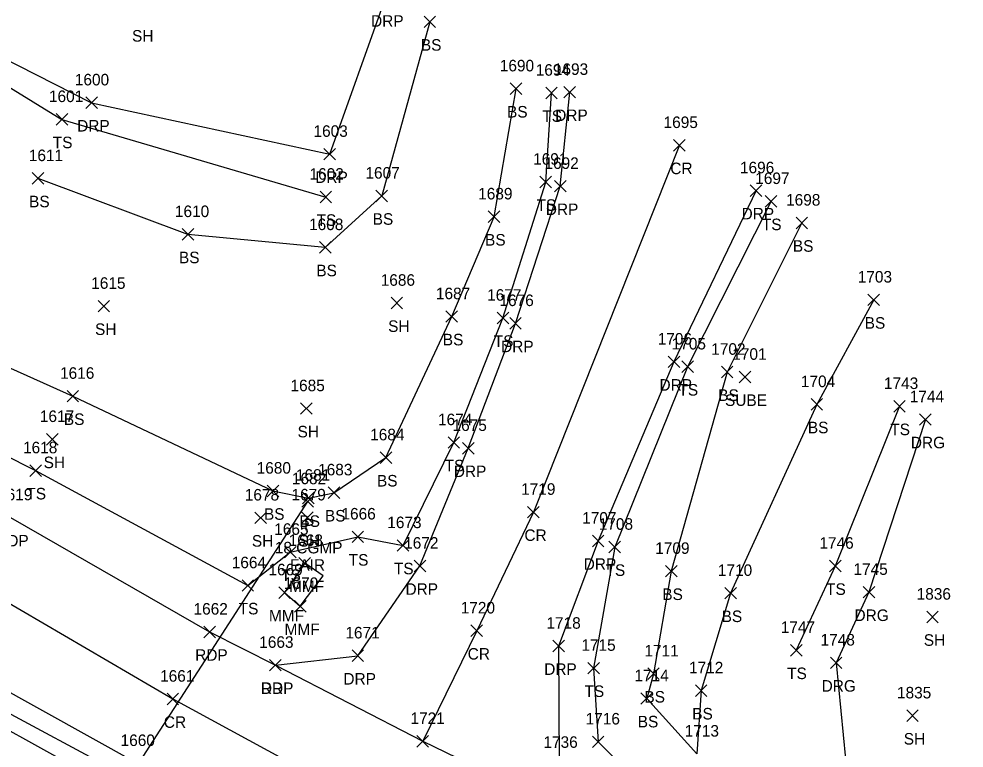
# Model space of a CAD drawing. Extents: x 1586965 to 1590952, y 716317 to 720029.
# Drawn here: x 1587975.1 to 1588139.1, y 719743.2 to 719869.6 of the extents above; entities that cross this region are included whole.
import ezdxf

# ---------------------------------------------------------------- set-up
doc = ezdxf.new("R2010")
doc.units = 0
for name, color, linetype in [('D_A', 7, 'Continuous'), ('D_C', 7, 'Continuous'), ('D_I', 7, 'Continuous'), ('D_TIC', 7, 'Continuous'), ('DCP', 7, 'Continuous'), ('L_A', 7, 'Continuous'), ('L_I', 7, 'Continuous'), ('L_TIC', 7, 'Continuous'), ('LDEFAULT', 7, 'Continuous'), ('LELB', 7, 'Continuous'), ('P_A', 7, 'Continuous'), ('P_I', 7, 'Continuous'), ('P_TIC', 7, 'Continuous'), ('PET', 7, 'Continuous'), ('PRC', 7, 'Continuous'), ('R_A', 7, 'Continuous'), ('R_I', 7, 'Continuous'), ('R_TIC', 7, 'Continuous'), ('RDG', 7, 'Continuous'), ('RDP', 7, 'Continuous'), ('U_A', 7, 'Continuous'), ('U_I', 7, 'Continuous'), ('U_TIC', 7, 'Continuous')]:
    doc.layers.add(name, color=color, linetype=linetype)

msp = doc.modelspace()

# ---------------------------------------------------------------- linework, layer by layer
at = {"layer": 'D_TIC'}
for points in [[(1588024.22, 719784.95), (1588026.22, 719786.95)], [(1588026.22, 719784.95), (1588024.22, 719786.95)]]:
    msp.add_lwpolyline(points, dxfattribs=at)
at = {"layer": 'DCP'}
msp.add_lwpolyline([(1587993.11, 719736.22), (1588025.22, 719785.95)], dxfattribs=at)
at = {"layer": 'L_TIC'}
for points in [[(1588045.42, 719868.11), (1588047.42, 719870.11)], [(1588047.42, 719868.11), (1588045.42, 719870.11)], [(1588060.37, 719856.52), (1588062.37, 719858.52)], [(1588062.37, 719856.52), (1588060.37, 719858.52)], [(1588066.52, 719855.77), (1588068.52, 719857.77)], [(1588068.52, 719855.77), (1588066.52, 719857.77)], [(1587981.59, 719851.2), (1587983.59, 719853.2)], [(1587983.59, 719851.2), (1587981.59, 719853.2)], [(1587977.45, 719840.96), (1587979.45, 719842.96)], [(1587979.45, 719840.96), (1587977.45, 719842.96)], [(1588065.51, 719840.34), (1588067.51, 719842.34)], [(1588067.51, 719840.34), (1588065.51, 719842.34)], [(1588027.36, 719837.74), (1588029.36, 719839.74)], [(1588029.36, 719837.74), (1588027.36, 719839.74)], [(1588037.06, 719837.93), (1588039.06, 719839.93)], [(1588039.06, 719837.93), (1588037.06, 719839.93)], [(1588104.6, 719836.99), (1588106.6, 719838.99)], [(1588106.6, 719836.99), (1588104.6, 719838.99)], [(1588056.55, 719834.32), (1588058.55, 719836.32)], [(1588058.55, 719834.32), (1588056.55, 719836.32)], [(1588109.95, 719833.25), (1588111.95, 719835.25)], [(1588111.95, 719833.25), (1588109.95, 719835.25)], [(1588003.45, 719831.26), (1588005.45, 719833.26)], [(1588005.45, 719831.26), (1588003.45, 719833.26)], [(1588027.28, 719829), (1588029.28, 719831)], [(1588029.28, 719829), (1588027.28, 719831)], [(1587988.85, 719818.82), (1587990.85, 719820.82)], [(1587990.85, 719818.82), (1587988.85, 719820.82)], [(1588039.69, 719819.35), (1588041.69, 719821.35)], [(1588041.69, 719819.35), (1588039.69, 719821.35)], [(1588122.41, 719819.91), (1588124.41, 719821.91)], [(1588124.41, 719819.91), (1588122.41, 719821.91)], [(1588049.21, 719817.02), (1588051.21, 719819.02)], [(1588051.21, 719817.02), (1588049.21, 719819.02)], [(1588058.09, 719816.76), (1588060.09, 719818.76)], [(1588060.09, 719816.76), (1588058.09, 719818.76)], [(1588090.13, 719808.31), (1588092.13, 719810.31)], [(1588092.13, 719808.31), (1588090.13, 719810.31)], [(1588097, 719807.39), (1588099, 719809.39)], [(1588099, 719807.39), (1588097, 719809.39)], [(1587983.49, 719803.22), (1587985.49, 719805.22)], [(1587985.49, 719803.22), (1587983.49, 719805.22)], [(1588023.98, 719801.07), (1588025.98, 719803.07)], [(1588025.98, 719801.07), (1588023.98, 719803.07)], [(1588112.55, 719801.78), (1588114.55, 719803.78)], [(1588114.55, 719801.78), (1588112.55, 719803.78)], [(1588126.88, 719801.45), (1588128.88, 719803.45)], [(1588128.88, 719801.45), (1588126.88, 719803.45)], [(1587979.94, 719795.73), (1587981.94, 719797.73)], [(1587981.94, 719795.73), (1587979.94, 719797.73)], [(1588049.57, 719795.18), (1588051.57, 719797.18)], [(1588051.57, 719795.18), (1588049.57, 719797.18)], [(1588037.8, 719792.55), (1588039.8, 719794.55)], [(1588039.8, 719792.55), (1588037.8, 719794.55)], [(1587977.02, 719790.31), (1587979.02, 719792.31)], [(1587979.02, 719790.31), (1587977.02, 719792.31)], [(1588018.19, 719786.78), (1588020.19, 719788.78)], [(1588020.19, 719786.78), (1588018.19, 719788.78)], [(1588028.77, 719786.48), (1588030.77, 719788.48)], [(1588030.77, 719786.48), (1588028.77, 719788.48)], [(1588024.35, 719785.55), (1588026.35, 719787.55)], [(1588026.35, 719785.55), (1588024.35, 719787.55)], [(1588016.05, 719782.12), (1588018.05, 719784.12)], [(1588018.05, 719782.12), (1588016.05, 719784.12)], [(1588024.17, 719782.14), (1588026.17, 719784.14)], [(1588026.17, 719782.14), (1588024.17, 719784.14)], [(1588032.93, 719778.83), (1588034.93, 719780.83)], [(1588034.93, 719778.83), (1588032.93, 719780.83)], [(1588021.21, 719776.17), (1588023.21, 719778.17)], [(1588023.21, 719776.17), (1588021.21, 719778.17)], [(1588040.77, 719777.33), (1588042.77, 719779.33)], [(1588042.77, 719777.33), (1588040.77, 719779.33)], [(1588077.49, 719777.05), (1588079.49, 719779.05)], [(1588079.49, 719777.05), (1588077.49, 719779.05)], [(1588023.71, 719774.24), (1588025.71, 719776.24)], [(1588025.71, 719774.24), (1588023.71, 719776.24)], [(1588087.3, 719772.87), (1588089.3, 719774.87)], [(1588089.3, 719772.87), (1588087.3, 719774.87)], [(1588115.74, 719773.76), (1588117.74, 719775.76)], [(1588117.74, 719773.76), (1588115.74, 719775.76)], [(1588013.84, 719770.38), (1588015.84, 719772.38)], [(1588015.84, 719770.38), (1588013.84, 719772.38)], [(1588020.21, 719769.15), (1588022.21, 719771.15)], [(1588022.21, 719769.15), (1588020.21, 719771.15)], [(1588097.59, 719769.05), (1588099.59, 719771.05)], [(1588099.59, 719769.05), (1588097.59, 719771.05)], [(1588022.93, 719766.79), (1588024.93, 719768.79)], [(1588024.93, 719766.79), (1588022.93, 719768.79)], [(1588132.61, 719764.93), (1588134.61, 719766.93)], [(1588134.61, 719764.93), (1588132.61, 719766.93)], [(1588108.98, 719759.16), (1588110.98, 719761.16)], [(1588110.98, 719759.16), (1588108.98, 719761.16)], [(1588073.83, 719756.06), (1588075.83, 719758.06)], [(1588075.83, 719756.06), (1588073.83, 719758.06)], [(1588084.2, 719755.09), (1588086.2, 719757.09)], [(1588086.2, 719755.09), (1588084.2, 719757.09)], [(1588092.49, 719752.16), (1588094.49, 719754.16)], [(1588094.49, 719752.16), (1588092.49, 719754.16)], [(1588083.04, 719750.79), (1588085.04, 719752.79)], [(1588085.04, 719750.79), (1588083.04, 719752.79)], [(1588083.04, 719750.79), (1588085.04, 719752.79)], [(1588085.04, 719750.79), (1588083.04, 719752.79)], [(1588129.14, 719747.81), (1588131.14, 719749.81)], [(1588131.14, 719747.81), (1588129.14, 719749.81)], [(1588074.62, 719743.29), (1588076.62, 719745.29)], [(1588076.62, 719743.29), (1588074.62, 719745.29)]]:
    msp.add_lwpolyline(points, dxfattribs=at)
at = {"layer": 'LDEFAULT'}
for points in [[(1588027.89, 719773.06), (1588024.71, 719775.24), (1588021.21, 719770.15), (1588023.93, 719767.79)], [(1588023.93, 719767.79), (1588027.89, 719773.06)]]:
    msp.add_lwpolyline(points, dxfattribs=at)
at = {"layer": 'LELB'}
for points in [[(1587811.93, 719949.52), (1587792.29, 719924.28), (1587790.61, 719906.24), (1587796.42, 719891.05), (1587800.94, 719879.86), (1587824.09, 719870.75), (1587863.89, 719860.75), (1587885.59, 719851.77), (1587915.12, 719838.63), (1587948, 719820.59), (1587984.49, 719804.22), (1588019.19, 719787.78), (1588025.35, 719786.55), (1588029.77, 719787.48), (1588038.8, 719793.55), (1588050.21, 719818.02), (1588057.55, 719835.32), (1588061.37, 719857.52)], [(1587811.93, 719949.52), (1587792.29, 719924.28), (1587790.61, 719906.24), (1587796.42, 719891.05), (1587800.94, 719879.86), (1587824.09, 719870.75), (1587863.89, 719860.75), (1587885.59, 719851.77), (1587915.12, 719838.63), (1587948, 719820.59), (1587984.49, 719804.22), (1588019.19, 719787.78), (1588025.35, 719786.55), (1588029.77, 719787.48), (1588038.8, 719793.55), (1588050.21, 719818.02), (1588057.55, 719835.32), (1588061.37, 719857.52)], [(1587980.38, 719907.57), (1587967.76, 719883.76), (1587958.41, 719867.03), (1587982.59, 719852.2), (1588028.36, 719838.74)], [(1587980.38, 719907.57), (1587967.76, 719883.76), (1587958.41, 719867.03), (1587982.59, 719852.2), (1588028.36, 719838.74)], [(1587785.92, 719905.04), (1587790.72, 719880.4), (1587795.97, 719870.23), (1587799.98, 719865.36), (1587821.67, 719859.64), (1587858.86, 719846.91), (1587879.62, 719839.86), (1587909.63, 719826.79), (1587942.7, 719809.1), (1587978.02, 719791.31), (1588014.84, 719771.38), (1588022.21, 719777.17), (1588033.93, 719779.83), (1588041.77, 719778.33), (1588050.57, 719796.18), (1588059.09, 719817.76), (1588066.51, 719841.34), (1588067.52, 719856.77)], [(1587785.92, 719905.04), (1587790.72, 719880.4), (1587795.97, 719870.23), (1587799.98, 719865.36), (1587821.67, 719859.64), (1587858.86, 719846.91), (1587879.62, 719839.86), (1587909.63, 719826.79), (1587942.7, 719809.1), (1587978.02, 719791.31), (1588014.84, 719771.38), (1588022.21, 719777.17), (1588033.93, 719779.83), (1588041.77, 719778.33), (1588050.57, 719796.18), (1588059.09, 719817.76), (1588066.51, 719841.34), (1588067.52, 719856.77)], [(1588046.42, 719869.11), (1588038.06, 719838.93), (1588028.28, 719830), (1588004.45, 719832.26), (1587978.45, 719841.96)], [(1588046.42, 719869.11), (1588038.06, 719838.93), (1588028.28, 719830), (1588004.45, 719832.26), (1587978.45, 719841.96)], [(1588105.6, 719837.99), (1588091.13, 719809.31), (1588078.49, 719778.05), (1588074.83, 719757.06), (1588075.62, 719744.29), (1588082.54, 719737.39), (1588094.48, 719728.45), (1588105.69, 719715.8), (1588135.44, 719702.09)], [(1588105.6, 719837.99), (1588091.13, 719809.31), (1588078.49, 719778.05), (1588074.83, 719757.06), (1588075.62, 719744.29), (1588082.54, 719737.39), (1588094.48, 719728.45), (1588105.69, 719715.8), (1588135.44, 719702.09)], [(1588110.95, 719834.25), (1588098, 719808.39), (1588088.3, 719773.87), (1588085.2, 719756.09), (1588084.04, 719751.79)], [(1588110.95, 719834.25), (1588098, 719808.39), (1588088.3, 719773.87), (1588085.2, 719756.09), (1588084.04, 719751.79)], [(1587769.54, 719828.25), (1587817.81, 719818.92), (1587845.39, 719810.87), (1587866.59, 719802.16), (1587894.5, 719791.41), (1587924.64, 719774.45), (1587960.66, 719756.07), (1587994.24, 719738.05), (1588029.81, 719715.93), (1588049.13, 719705.79), (1588061.35, 719699.86), (1588090.7, 719682.25), (1588125.12, 719667.08), (1588163.84, 719653.66), (1588168.64, 719652.01), (1588170.5, 719647.84), (1588169.34, 719638.56), (1588158.94, 719617.68), (1588144.69, 719590.38)], [(1587769.54, 719828.25), (1587817.81, 719818.92), (1587845.39, 719810.87), (1587866.59, 719802.16), (1587894.5, 719791.41), (1587924.64, 719774.45), (1587960.66, 719756.07), (1587994.24, 719738.05), (1588029.81, 719715.93), (1588049.13, 719705.79), (1588061.35, 719699.86), (1588090.7, 719682.25), (1588125.12, 719667.08), (1588163.84, 719653.66), (1588168.64, 719652.01), (1588170.5, 719647.84), (1588169.34, 719638.56), (1588158.94, 719617.68), (1588144.69, 719590.38)], [(1588123.41, 719820.91), (1588113.55, 719802.78), (1588098.59, 719770.05), (1588093.49, 719753.16), (1588092.75, 719742.19), (1588084.04, 719751.79)], [(1588123.41, 719820.91), (1588113.55, 719802.78), (1588098.59, 719770.05), (1588093.49, 719753.16), (1588092.75, 719742.19), (1588084.04, 719751.79)], [(1588127.88, 719802.45), (1588116.74, 719774.76), (1588109.98, 719760.16)], [(1588127.88, 719802.45), (1588116.74, 719774.76), (1588109.98, 719760.16)], [(1587893.61, 719788.22), (1587923.32, 719772.46), (1587959.45, 719753.99), (1587990.31, 719736.86), (1587992.49, 719736.59), (1587993.47, 719735.49), (1587996.7, 719733.15), (1588001.37, 719729.89), (1588028.07, 719713.52), (1588047.21, 719701.72), (1588059.27, 719695.66), (1588101.54, 719672.79), (1588123.97, 719663.55), (1588153.31, 719655.21), (1588167.62, 719650.14)], [(1587893.61, 719788.22), (1587923.32, 719772.46), (1587959.45, 719753.99), (1587990.31, 719736.86), (1587992.49, 719736.59), (1587993.47, 719735.49), (1587996.7, 719733.15), (1588001.37, 719729.89), (1588028.07, 719713.52), (1588047.21, 719701.72), (1588059.27, 719695.66), (1588101.54, 719672.79), (1588123.97, 719663.55), (1588153.31, 719655.21), (1588167.62, 719650.14)]]:
    msp.add_lwpolyline(points, dxfattribs=at)
at = {"layer": 'P_TIC'}
for points in [[(1588088.7, 719846.7), (1588090.7, 719848.7)], [(1588090.7, 719846.7), (1588088.7, 719848.7)], [(1588063.38, 719783.11), (1588065.38, 719785.11)], [(1588065.38, 719783.11), (1588063.38, 719785.11)], [(1588007.21, 719762.34), (1588009.21, 719764.34)], [(1588009.21, 719762.34), (1588007.21, 719764.34)], [(1588053.55, 719762.54), (1588055.55, 719764.54)], [(1588055.55, 719762.54), (1588053.55, 719764.54)], [(1588018.61, 719756.58), (1588020.61, 719758.58)], [(1588020.61, 719756.58), (1588018.61, 719758.58)], [(1588000.84, 719750.71), (1588002.84, 719752.71)], [(1588002.84, 719750.71), (1588000.84, 719752.71)], [(1588044.18, 719743.38), (1588046.18, 719745.38)], [(1588046.18, 719743.38), (1588044.18, 719745.38)], [(1588044.18, 719743.38), (1588046.18, 719745.38)], [(1588046.18, 719743.38), (1588044.18, 719745.38)]]:
    msp.add_lwpolyline(points, dxfattribs=at)
at = {"layer": 'PET'}
for points in [[(1587795.98, 719858.74), (1587820.3, 719853.13), (1587857.37, 719841.42), (1587877.69, 719833.83), (1587907.04, 719819.84), (1587939.32, 719802.03), (1587973.69, 719783.16), (1588008.21, 719763.34), (1588019.61, 719757.58), (1588045.18, 719744.38), (1588072.84, 719731.02), (1588081.8, 719723.85), (1588104.43, 719712.22), (1588133.68, 719697.26), (1588170.87, 719681.39), (1588198.42, 719670.99), (1588228.28, 719659.25)], [(1587769.59, 719834.05), (1587819.16, 719826.14), (1587848.36, 719816.77), (1587868.73, 719807.9), (1587895.82, 719795.75), (1587926.99, 719779.02), (1587962.24, 719759.15), (1587995.65, 719740.56), (1588031.83, 719719.54), (1588060.89, 719703.68), (1588093.53, 719688.06), (1588127.35, 719672.7), (1588165.1, 719657.02), (1588195.68, 719645.12), (1588212.38, 719637.86), (1588219.86, 719635.29)]]:
    msp.add_lwpolyline(points, dxfattribs=at)
at = {"layer": 'PRC'}
for points in [[(1588089.7, 719847.7), (1588064.38, 719784.11), (1588054.55, 719763.54), (1588045.18, 719744.38)], [(1588089.7, 719847.7), (1588064.38, 719784.11), (1588054.55, 719763.54), (1588045.18, 719744.38)], [(1587770.57, 719846.88), (1587822.37, 719838.71), (1587852.49, 719828.95), (1587873.58, 719820.04), (1587901.35, 719807.55), (1587933.49, 719790.19), (1587967.95, 719771.53), (1588001.84, 719751.71), (1588038.72, 719731.7), (1588068.79, 719715.56), (1588099.02, 719700.65), (1588127.2, 719686.75), (1588167.73, 719669.46), (1588194.58, 719658.84), (1588224.51, 719647.27)], [(1587770.57, 719846.88), (1587822.37, 719838.71), (1587852.49, 719828.95), (1587873.58, 719820.04), (1587901.35, 719807.55), (1587933.49, 719790.19), (1587967.95, 719771.53), (1588001.84, 719751.71), (1588038.72, 719731.7), (1588068.79, 719715.56), (1588099.02, 719700.65), (1588127.2, 719686.75), (1588167.73, 719669.46), (1588194.58, 719658.84), (1588224.51, 719647.27)]]:
    msp.add_lwpolyline(points, dxfattribs=at)
at = {"layer": 'R_TIC'}
for points in [[(1588069.67, 719855.91), (1588071.67, 719857.91)], [(1588071.67, 719855.91), (1588069.67, 719857.91)], [(1587986.74, 719854.09), (1587988.74, 719856.09)], [(1587988.74, 719854.09), (1587986.74, 719856.09)], [(1588028.05, 719845.17), (1588030.05, 719847.17)], [(1588030.05, 719845.17), (1588028.05, 719847.17)], [(1588068.04, 719839.61), (1588070.04, 719841.61)], [(1588070.04, 719839.61), (1588068.04, 719841.61)], [(1588102, 719838.85), (1588104, 719840.85)], [(1588104, 719838.85), (1588102, 719840.85)], [(1588060.28, 719815.83), (1588062.28, 719817.83)], [(1588062.28, 719815.83), (1588060.28, 719817.83)], [(1588087.76, 719809.16), (1588089.76, 719811.16)], [(1588089.76, 719809.16), (1588087.76, 719811.16)], [(1588131.37, 719799.17), (1588133.37, 719801.17)], [(1588133.37, 719799.17), (1588131.37, 719801.17)], [(1588052.09, 719794.18), (1588054.09, 719796.18)], [(1588054.09, 719794.18), (1588052.09, 719796.18)], [(1588074.61, 719778.11), (1588076.61, 719780.11)], [(1588076.61, 719778.11), (1588074.61, 719780.11)], [(1588043.7, 719773.77), (1588045.7, 719775.77)], [(1588045.7, 719773.77), (1588043.7, 719775.77)], [(1588121.59, 719769.23), (1588123.59, 719771.23)], [(1588123.59, 719769.23), (1588121.59, 719771.23)], [(1588067.76, 719759.89), (1588069.76, 719761.89)], [(1588069.76, 719759.89), (1588067.76, 719761.89)], [(1588032.93, 719758.21), (1588034.93, 719760.21)], [(1588034.93, 719758.21), (1588032.93, 719760.21)], [(1588018.61, 719756.58), (1588020.61, 719758.58)], [(1588020.61, 719756.58), (1588018.61, 719758.58)], [(1588115.89, 719756.98), (1588117.89, 719758.98)], [(1588117.89, 719756.98), (1588115.89, 719758.98)]]:
    msp.add_lwpolyline(points, dxfattribs=at)
at = {"layer": 'RDG'}
msp.add_lwpolyline([(1588132.37, 719800.17), (1588122.59, 719770.23), (1588116.89, 719757.98), (1588119.75, 719728.86)], dxfattribs=at)
at = {"layer": 'RDP'}
for points in [[(1587981.59, 719906.83), (1587969.62, 719882.82), (1587961.99, 719868.1), (1587987.74, 719855.09), (1588029.05, 719846.17), (1588038.73, 719873.26)], [(1588019.61, 719757.58), (1588033.93, 719759.21), (1588044.7, 719774.77), (1588053.09, 719795.18), (1588061.28, 719816.83), (1588069.04, 719840.61), (1588070.67, 719856.91)], [(1588103, 719839.85), (1588088.76, 719810.16), (1588075.61, 719779.11), (1588068.76, 719760.89), (1588068.87, 719740.24), (1588072.84, 719731.02)]]:
    msp.add_lwpolyline(points, dxfattribs=at)
at = {"layer": 'U_TIC'}
for points in [[(1588100.09, 719806.52), (1588102.09, 719808.52)], [(1588102.09, 719806.52), (1588100.09, 719808.52)]]:
    msp.add_lwpolyline(points, dxfattribs=at)

# ---------------------------------------------------------------- texts
at = {"layer": 'D_A'}
msp.add_text('P', height=2, dxfattribs=at).set_placement((1588024.6, 719780.95))
at = {"layer": 'D_C'}
for s, p in [('18 CGMP', (1588019.52, 719776.95)), (' FAIR', (1588021.4, 719773.95))]:
    msp.add_text(s, height=2, dxfattribs=at).set_placement(p)
at = {"layer": 'D_I'}
msp.add_text('1682', height=2, dxfattribs=at).set_placement((1588022.48, 719788.95))
at = {"layer": 'L_A'}
for s, p in [('SH', (1587994.75, 719865.68)), ('BS', (1588044.86, 719864.11)), ('BS', (1588059.81, 719852.52)), ('TS', (1588065.93, 719851.77)), ('TS', (1587981, 719847.2)), ('BS', (1587976.89, 719836.96)), ('TS', (1588064.92, 719836.34)), ('TS', (1588026.77, 719833.74)), ('BS', (1588036.5, 719833.93)), ('TS', (1588104.01, 719832.99)), ('BS', (1588055.99, 719830.32)), ('BS', (1588109.39, 719829.25)), ('BS', (1588002.89, 719827.26)), ('BS', (1588026.72, 719825)), ('BS', (1588121.85, 719815.91)), ('SH', (1587988.33, 719814.82)), ('SH', (1588039.18, 719815.35)), ('BS', (1588048.66, 719813.02)), ('TS', (1588057.5, 719812.76)), ('TS', (1588089.54, 719804.31)), ('BS', (1588096.44, 719803.39)), ('BS', (1587982.93, 719799.22)), ('BS', (1588111.99, 719797.78)), ('TS', (1588126.29, 719797.45)), ('SH', (1588023.47, 719797.07)), ('SH', (1587979.42, 719791.73)), ('TS', (1588048.98, 719791.18)), ('BS', (1588037.24, 719788.55)), ('TS', (1587976.42, 719786.31)), ('BS', (1588017.64, 719782.78)), ('BS', (1588023.79, 719781.55)), ('BS', (1588028.21, 719782.48)), ('SH', (1588015.54, 719778.12)), ('SH', (1588023.66, 719778.14)), ('TS', (1588032.34, 719774.83)), ('TS', (1588040.18, 719773.33)), ('TS', (1588076.89, 719773.05)), ('TS', (1588020.62, 719772.17)), ('MMF', (1588021.99, 719770.24)), ('TS', (1588115.15, 719769.76)), ('BS', (1588086.74, 719768.87)), ('TS', (1588013.25, 719766.38)), ('MMF', (1588018.5, 719765.15)), ('BS', (1588097.03, 719765.05)), ('MMF', (1588021.21, 719762.79)), ('SH', (1588132.1, 719760.93)), ('TS', (1588108.39, 719755.16)), ('TS', (1588073.24, 719752.06)), ('BS', (1588083.64, 719751.09)), ('BS', (1588082.48, 719746.79)), ('BS', (1588082.48, 719746.79)), ('BS', (1588091.93, 719748.16)), ('SH', (1588128.63, 719743.81))]:
    msp.add_text(s, height=2, dxfattribs=at).set_placement(p)
at = {"layer": 'L_I'}
for s, p in [('1690', (1588058.55, 719860.52)), ('1694', (1588064.78, 719859.77)), ('1601', (1587980.34, 719855.2)), ('1611', (1587976.85, 719844.96)), ('1691', (1588064.33, 719844.34)), ('1602', (1588025.54, 719841.74)), ('1607', (1588035.24, 719841.93)), ('1697', (1588102.86, 719840.99)), ('1689', (1588054.8, 719838.32)), ('1698', (1588108.21, 719837.25)), ('1610', (1588002.19, 719835.26)), ('1608', (1588025.46, 719833)), ('1703', (1588120.64, 719823.91)), ('1615', (1587987.67, 719822.82)), ('1686', (1588037.89, 719823.35)), ('1687', (1588047.47, 719821.02)), ('1677', (1588056.35, 719820.76)), ('1705', (1588088.36, 719812.31)), ('1702', (1588095.23, 719811.39)), ('1616', (1587982.26, 719807.22)), ('1704', (1588110.78, 719805.78)), ('1685', (1588022.24, 719805.07)), ('1743', (1588125.19, 719805.45)), ('1617', (1587978.76, 719799.73)), ('1674', (1588047.83, 719799.18)), ('1684', (1588036.06, 719796.55)), ('1618', (1587975.84, 719794.31)), ('1680', (1588016.37, 719790.78)), ('1681', (1588023.18, 719789.55)), ('1683', (1588027.03, 719790.48)), ('1678', (1588014.31, 719786.12)), ('1679', (1588022.42, 719786.14)), ('1666', (1588031.08, 719782.83)), ('1673', (1588039.03, 719781.33)), ('1708', (1588075.71, 719781.05)), ('1665', (1588019.42, 719780.17)), ('1668', (1588021.92, 719778.24)), ('1746', (1588113.99, 719777.76)), ('1709', (1588085.52, 719776.87)), ('1664', (1588012.05, 719774.38)), ('1669', (1588018.42, 719773.15)), ('1710', (1588096.38, 719773.05)), ('1670', (1588021.1, 719770.79)), ('1836', (1588130.86, 719768.93)), ('1747', (1588107.29, 719763.16)), ('1715', (1588072.7, 719760.06)), ('1711', (1588083.64, 719759.09)), ('1714', (1588081.91, 719754.79)), ('1714', (1588081.91, 719754.79)), ('1712', (1588091.37, 719756.16)), ('1835', (1588127.45, 719751.81)), ('1716', (1588073.44, 719747.29)), ('1713', (1588090.62, 719745.19))]:
    msp.add_text(s, height=2, dxfattribs=at).set_placement(p)
at = {"layer": 'P_A'}
for s, p in [('CR', (1588088.13, 719842.7)), ('RDP', (1587971.18, 719778.16)), ('CR', (1588062.82, 719779.11)), ('RDP', (1588005.7, 719758.34)), ('CR', (1588052.98, 719758.54)), ('RDP', (1588017.1, 719752.58)), ('CR', (1588000.27, 719746.71))]:
    msp.add_text(s, height=2, dxfattribs=at).set_placement(p)
at = {"layer": 'P_I'}
for s, p in [('1695', (1588086.96, 719850.7)), ('1619', (1587971.51, 719786.16)), ('1719', (1588062.25, 719787.11)), ('1662', (1588005.42, 719766.34)), ('1720', (1588051.77, 719766.54)), ('1663', (1588016.82, 719760.58)), ('1661', (1587999.62, 719754.71)), ('1721', (1588043.06, 719747.38)), ('1721', (1588043.06, 719747.38)), ('1660', (1587992.77, 719743.56))]:
    msp.add_text(s, height=2, dxfattribs=at).set_placement(p)
at = {"layer": 'R_A'}
for s, p in [('DRP', (1588036.22, 719868.26)), ('DRP', (1588068.16, 719851.91)), ('DRP', (1587985.23, 719850.09)), ('DRP', (1588026.54, 719841.17)), ('DRP', (1588066.53, 719835.61)), ('DRP', (1588100.49, 719834.85)), ('DRP', (1588058.77, 719811.83)), ('DRP', (1588086.25, 719805.16)), ('DRG', (1588129.85, 719795.17)), ('DRP', (1588050.57, 719790.18)), ('DRP', (1588073.1, 719774.11)), ('DRP', (1588042.19, 719769.77)), ('DRG', (1588120.08, 719765.23)), ('DRP', (1588066.25, 719755.89)), ('DRP', (1588031.42, 719754.21)), ('DRP', (1588017.1, 719752.58)), ('DRG', (1588114.38, 719752.98))]:
    msp.add_text(s, height=2, dxfattribs=at).set_placement(p)
at = {"layer": 'R_I'}
for s, p in [('1693', (1588067.93, 719859.91)), ('1600', (1587984.83, 719858.09)), ('1603', (1588026.23, 719849.17)), ('1692', (1588066.3, 719843.61)), ('1696', (1588100.21, 719842.85)), ('1676', (1588058.49, 719819.83)), ('1706', (1588085.94, 719813.16)), ('1744', (1588129.67, 719803.17)), ('1675', (1588050.35, 719798.18)), ('1707', (1588072.84, 719782.11)), ('1672', (1588041.96, 719777.77)), ('1745', (1588119.9, 719773.23)), ('1718', (1588066.64, 719763.89)), ('1671', (1588031.76, 719762.21)), ('1663', (1588016.82, 719760.58)), ('1748', (1588114.2, 719760.98)), ('1736', (1588066.12, 719743.24))]:
    msp.add_text(s, height=2, dxfattribs=at).set_placement(p)
at = {"layer": 'U_A'}
msp.add_text('SUBE', height=2, dxfattribs=at).set_placement((1588097.62, 719802.52))
at = {"layer": 'U_I'}
msp.add_text('1701', height=2, dxfattribs=at).set_placement((1588098.88, 719810.52))

doc.saveas('drawing.dxf')
